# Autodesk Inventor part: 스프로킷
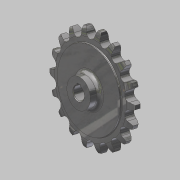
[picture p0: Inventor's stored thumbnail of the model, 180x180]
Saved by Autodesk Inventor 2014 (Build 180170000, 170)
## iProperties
Created: 2016-03
Part Number: 스프로킷
Material: 강철, 탄소
Document SubType Name: Modeling
Designer: mduedu
Density: 7.87 g/cm^3
Appearance: 반광택
Author: mduedu
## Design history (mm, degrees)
sketch "스케치1"
  geometry: L1 (0, 5)-(29.5, 5); L2 (29.5, 5)-(29.5, 4.1); L3 (30, 3.6)-(33.625, 3.6); L4 (40, 2)-(40, 0); L5 (40, 0)-(0, 0); L6 (0, 0)-(0, 5); L7 (0, -5)-(29.5, -5); L8 (29.5, -5)-(29.5, -4.1); L9 (30, -3.6)-(33.625, -3.6); L10 (40, -2)-(40, 0); L11 (0, 0)-(0, -5); A1 r 13.5 centre (33.625, -9.9) between (40, 2) and (33.625, 3.6); A2 r 13.5 centre (33.625, 9.9) between (33.625, -3.6) and (40, -2); A3 r 0.5 centre (30, 4.1) between (29.5, 4.1) and (30, 3.6); A4 r 0.5 centre (30, -4.1) between (30, -3.6) and (29.5, -4.1); 2 further points
  constraints: 22 end point, 8 point on circle, 6 symmetric about line, 5 tangent, 4 centre point, 4 parallel, 4 point on line, 1 equal radius, 1 horizontal, 1 perpendicular, 1 other
  dimensions: "d0" = 80 diameter of L4 L6; "d2" = 59 diameter of L2 L6; "d3" = 1.6 vertical distance of L4.start L3.end; "d4" = 3.6 distance from line of L4.end L3; "d5" = 5 distance between parallel lines of L5 L1; "d6" = 13.5 radius of A1; "d15" = 0.5 radius of A3
revolve "회전1" sketch "스케치1" stored, may be unused: angle "d7" = 90 deg
sketch "스케치2" dims "d8" = 65.2, "d11" = 80
  geometry: L1 (0, 0)-(0, 32.6); A1 r 36.57 centre (0, 0) between (-16.231, 32.771) and (0, 36.57); A2 r 3.97 centre (0, 36.57) between (-3.866, 35.665) and (0, 32.6); A3 r 12.7 centre (-16.231, 32.771) between (-3.866, 35.665) and (-5.534, 39.615); A4 r 12.7 centre (16.231, 32.771) between (5.534, 39.615) and (3.866, 35.665); A5 r 3.97 centre (0, 36.57) between (0, 32.6) and (3.866, 35.665); A6 r 40 centre (0, 0) between (5.534, 39.615) and (-5.534, 39.615); 2 further points
  constraints: 12 point on circle, 6 centre point, 4 coincident, 3 symmetric about line, 2 end point, 1 point on line, 1 tangent, 1 vertical, 1 vertical alignment, 7 other
  dimensions: "d10" = 73.14 diameter of A1; "d12" = 12.7 radius of A3
extrude "돌출1" cut sketch "스케치2" stored distance "d13" = 10; taper "d14" = 0 deg
sketch "스케치3"
  geometry: C1 r 11 at (0, 0); 1 further point
  constraints: 1 centre point, 1 coincident
  dimensions: "d19" = 22 diameter of C1
extrude "돌출2" join sketch "스케치3" distance "d20" = 8; taper "d21" = 0 deg
fillet "모깎기1" dims "d22" = 3
sketch "스케치4"
  geometry: L1 (-1.5, 0)-(1.5, 0); L2 (1.5, 0)-(1.5, 6.4); L3 (1.5, 6.4)-(-1.5, 6.4); L4 (-1.5, 6.4)-(-1.5, 0); C1 r 5 at (0, 0); 2 further points
  constraints: 8 end point, 2 coincident, 2 parallel, 1 centre point, 1 horizontal, 1 midpoint, 1 perpendicular
  dimensions: "d23" = 10 diameter of C1; "d25" = 3 distance of L2.end L3.end; "d26" = 6.4 distance of L1.end L2.end
extrude "돌출3" cut sketch "스케치4" stored distance "d27" = 8; taper "d28" = 0 deg
chamfer "모따기1" distance "d29" = 0.5; stored, may be unused: second distance "d30" = 2, angle "d31" = 45 deg
node "솔리드1"
pattern_circular "원형 패턴1" dims angle "d17" = 360 deg
